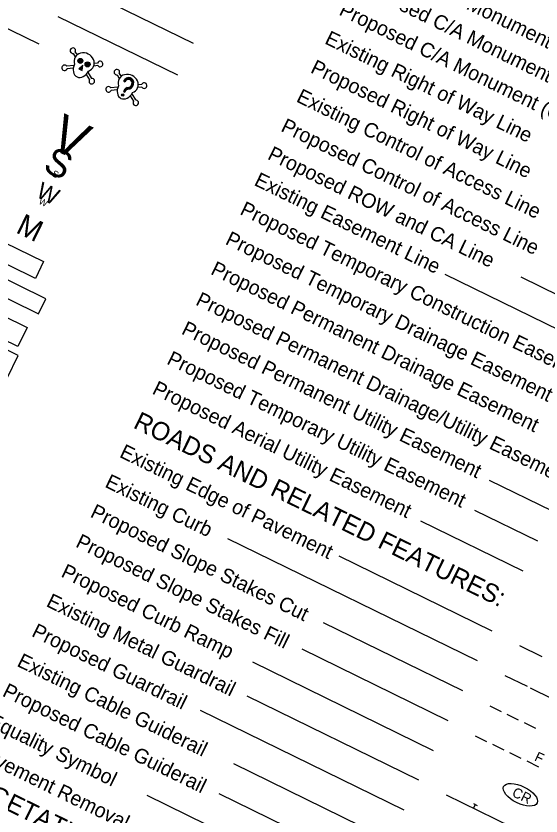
# Model space of a CAD drawing. Extents: x 1517888 to 1526099, y 633375 to 640181.
# Drawn here: x 1522960 to 1523591, y 635991 to 636952 of the extents above; entities that cross this region are included whole.
import ezdxf

# ---------------------------------------------------------------- set-up
doc = ezdxf.new("R2010")
doc.units = 0
doc.layers.add('Default', color=7, linetype='Continuous')

msp = doc.modelspace()

# ---------------------------------------------------------------- linework, layer by layer
at = {"layer": 'Default'}
for p, q in [((1523029.23, 636989.36), (1523172.88, 636919.11)), ((1523010.54, 636951.16), (1523154.2, 636880.91)), ((1522987.81, 636917.75), (1522932.43, 636944.84)), ((1523028.68, 636906.74), (1523031.29, 636902.53)), ((1523031.33, 636908.38), (1523033.44, 636904.98)), ((1523029.74, 636892.25), (1523021.15, 636891.33)), ((1523039.81, 636891.75), (1523039.81, 636891.75)), ((1523058.47, 636892.17), (1523053.54, 636891.65)), ((1523058.14, 636895.28), (1523054.15, 636894.85)), ((1523028.95, 636889.03), (1523021.48, 636888.23)), ((1523044.32, 636881.51), (1523048.28, 636875.12)), ((1523046.38, 636884.11), (1523050.93, 636876.77)), ((1523081.53, 636880.9), (1523084.13, 636876.69)), ((1523084.18, 636882.54), (1523086.29, 636879.13)), ((1523089.24, 636873.55), (1523091.02, 636872.68)), ((1523082.58, 636866.4), (1523073.99, 636865.49)), ((1523081.79, 636863.18), (1523074.32, 636862.39)), ((1523090, 636862.75), (1523089.24, 636861.18)), ((1523089.24, 636861.18), (1523091.02, 636860.31)), ((1523090.25, 636862.63), (1523089.49, 636861.06)), ((1523090.51, 636862.5), (1523089.74, 636860.94)), ((1523090.76, 636862.38), (1523090, 636860.81)), ((1523091.02, 636862.25), (1523090.25, 636860.69)), ((1523091.27, 636862.13), (1523090.51, 636860.56)), ((1523091.53, 636862), (1523090.76, 636860.44)), ((1523091.78, 636861.88), (1523091.02, 636860.31)), ((1523093.1, 636866.82), (1523093.1, 636866.82)), ((1523111.31, 636866.33), (1523106.39, 636865.81)), ((1523110.98, 636869.43), (1523106.99, 636869.01)), ((1523097.16, 636855.67), (1523101.12, 636849.28)), ((1523099.22, 636858.27), (1523103.77, 636850.92)), ((1523691.95, 636535.62), (1523475.96, 636641.25)), ((1523709.43, 636568.49), (1523566.93, 636638.18)), ((1523604.6, 636357.02), (1523528.94, 636394.02)), ((1523587.03, 636321.11), (1523511.37, 636358.11)), ((1523569.47, 636285.19), (1523446.55, 636345.31)), ((1523514.59, 636177.35), (1523214.45, 636324.15)), ((1523532.15, 636213.27), (1523348.37, 636303.15)), ((1523497.03, 636141.44), (1523329.69, 636223.28)), ((1523479.46, 636105.53), (1523303.96, 636191.36)), ((1523564.92, 636195.96), (1523591.86, 636182.79)), ((1523461.9, 636069.62), (1523244.76, 636175.81)), ((1523547.36, 636160.05), (1523574.29, 636146.88)), ((1523577.88, 636145.12), (1523604.82, 636131.95)), ((1523444.16, 636034.06), (1523237.95, 636134.91)), ((1523529.38, 636123.28), (1523543.02, 636116.61)), ((1523426.59, 635998.14), (1523181.96, 636117.79)), ((1523564.03, 636106.33), (1523550.47, 636112.96)), ((1523584.68, 636096.23), (1523571.03, 636102.91)), ((1523511.81, 636087.37), (1523525.46, 636080.7)), ((1523546.47, 636070.42), (1523532.91, 636077.05)), ((1523567.12, 636060.32), (1523553.47, 636067)), ((1523409.03, 635962.23), (1523221.74, 636053.83)), ((1523588.22, 636050), (1523574.21, 636056.85)), ((1523373.9, 635890.41), (1523117.8, 636015.66)), ((1523391.46, 635926.32), (1523204.18, 636017.92)), ((1523476.93, 636016.75), (1523620.58, 635946.49)), ((1523509.89, 636006.19), (1523514.38, 636003.99)), ((1523509.94, 636000.6), (1523512.14, 636005.09))]:
    msp.add_line(p, q, dxfattribs=at)
for points in [[(1523040.25, 636892.67), (1523035.65, 636888.25), (1523039.59, 636886.32)], [(1523039.81, 636891.75), (1523036.26, 636888.35), (1523039.3, 636886.86)], [(1523039.36, 636890.84), (1523036.86, 636888.44), (1523039, 636887.39)], [(1523038.91, 636889.93), (1523037.46, 636888.53), (1523038.7, 636887.93)], [(1523038.47, 636889.01), (1523038.07, 636888.63), (1523038.41, 636888.46)], [(1522930.35, 636687.5), (1522993.2, 636656.76), (1522983.37, 636636.67), (1522920.53, 636667.41)], [(1522888.47, 636642.48), (1522987.23, 636594.18), (1522996.01, 636612.13), (1522897.25, 636660.43)], [(1522882.32, 636622.4), (1522973.65, 636577.73), (1522962.41, 636554.75), (1522871.08, 636599.41)], [(1522850.74, 636565.33), (1522949.5, 636517.03), (1522962.68, 636543.97), (1522937.24, 636556.4), (1522930.66, 636542.94), (1522882.76, 636566.36), (1522889.35, 636579.83), (1522863.92, 636592.27)]]:
    msp.add_lwpolyline(points, close=True, dxfattribs=at)
for centre, radius in [((1523037.42, 636897.84), 2.97), ((1523037.42, 636897.84), 2.62), ((1523037.42, 636897.84), 2.27), ((1523037.42, 636897.84), 1.92), ((1523037.42, 636897.84), 1.57), ((1523037.42, 636897.84), 1.22), ((1523037.42, 636897.84), 0.867), ((1523037.42, 636897.84), 0.518), ((1523037.42, 636897.84), 0.168), ((1523046.08, 636893.61), 2.97), ((1523046.08, 636893.61), 2.62), ((1523046.08, 636893.61), 2.27), ((1523046.08, 636893.61), 1.92), ((1523046.08, 636893.61), 1.57), ((1523046.08, 636893.61), 1.22), ((1523046.08, 636893.61), 0.867), ((1523046.08, 636893.61), 0.518), ((1523046.08, 636893.61), 0.168), ((1523088.3, 636856.85), 1.42), ((1523088.3, 636856.85), 1.1), ((1523088.3, 636856.85), 0.781), ((1523088.3, 636856.85), 0.466), ((1523088.3, 636856.85), 0.151)]:
    msp.add_circle(centre, radius, dxfattribs=at)
for centre, start, end in [((1523028.47, 636910.05), 329.83534, 273.7439), ((1523018.4, 636889.47), 34.13155, 338.04011), ((1523061.21, 636894.04), 214.13155, 158.04011), ((1523081.31, 636884.21), 329.83534, 273.7439), ((1523051.15, 636873.46), 149.83534, 93.7439), ((1523114.05, 636868.19), 214.13155, 158.04011), ((1523071.25, 636863.63), 34.13155, 338.04011), ((1523103.99, 636847.61), 149.83534, 93.7439)]:
    msp.add_arc(centre, 3.32, start, end, dxfattribs=at)
for centre, major_axis, ratio, start_param, end_param in [((1523041.98, 636896.2), (11.17, -5.46), 0.885014, 5.564242, 10.143721), ((1523038.85, 636889.8), (-5.46, -11.17), 0.752542, 4.722735, 7.843636), ((1523094.82, 636870.35), (11.17, -5.46), 0.885014, 5.564242, 10.143721), ((1523095.01, 636870.73), (3.14, 6.41), 0.9, 3.567618, 7.853982), ((1523095.01, 636870.73), (3, 6.13), 0.9, 3.567618, 7.853982), ((1523095.01, 636870.73), (2.86, 5.85), 0.9, 3.567618, 7.853982), ((1523095.01, 636870.73), (2.72, 5.56), 0.9, 3.567618, 7.853982), ((1523095.01, 636870.73), (2.58, 5.28), 0.9, 3.567618, 7.853982), ((1523095.01, 636870.73), (2.44, 5), 0.9, 3.567618, 7.853982), ((1523095.01, 636870.73), (2.31, 4.71), 0.9, 3.567618, 7.853982), ((1523095.01, 636870.73), (2.17, 4.43), 0.9, 3.567618, 7.853982), ((1523091.69, 636863.96), (-5.46, -11.17), 0.752542, 4.722735, 7.843636), ((1523094.33, 636860.63), (2.35, 4.81), 0.9, 0.426026, 1.570796), ((1523094.33, 636860.63), (2.21, 4.53), 0.9, 0.426026, 1.570796), ((1523094.33, 636860.63), (2.07, 4.24), 0.9, 0.426026, 1.570796), ((1523094.33, 636860.63), (1.94, 3.96), 0.9, 0.426026, 1.570796), ((1523094.33, 636860.63), (1.8, 3.68), 0.9, 0.426026, 1.570796), ((1523094.33, 636860.63), (1.66, 3.39), 0.9, 0.426026, 1.570796), ((1523094.33, 636860.63), (1.52, 3.11), 0.9, 0.426026, 1.570796), ((1523094.33, 636860.63), (1.38, 2.83), 0.9, 0.426026, 1.570796)]:
    msp.add_ellipse(centre, major_axis=major_axis, ratio=ratio, start_param=start_param, end_param=end_param, dxfattribs=at)
msp.add_ellipse((1523566.17, 636016.69), major_axis=(20.14, -9.85), ratio=0.462467, dxfattribs=at)

# ---------------------------------------------------------------- texts
for s, height, p in [('Existing Permanent Easement Monument', 17.4903, (1523422.14, 637106.51)), ('Proposed Permanent Easement Monument', 17.4903, (1523406.19, 637073.73)), ('Existing C/A Monument', 17.4903, (1523379.74, 637019.54)), ('Proposed C/A Monument (Rebar and Cap)', 17.4903, (1523363.29, 636986.85)), ('Proposed C/A Monument (Concrete)', 17.4903, (1523347.04, 636953.61)), ('Existing Right of Way Line', 17.4903, (1523329.87, 636919.12)), ('Proposed Right of Way Line', 17.4903, (1523312.85, 636884.33)), ('Existing Control of Access Line', 17.4903, (1523295.76, 636849.38)), ('V', 44.97, (1522998.01, 636794.79)), ('Proposed Control of Access Line', 17.4903, (1523277.23, 636813.98)), ('Proposed ROW and CA Line', 17.4903, (1523261.2, 636780.42)), ('S', 32.98, (1522990.98, 636766.65)), ('S', 8, (1523002.56, 636759.79)), ('Existing Easement Line', 17.4903, (1523245.09, 636749.13)), ('W', 19.99, (1522982.9, 636735.12)), ('W', 8, (1522986.63, 636726.76)), ('Proposed Temporary Construction Easement', 17.4903, (1523228.01, 636714.2)), ('M', 25.49, (1522958.75, 636692.27)), ('Proposed Temporary Drainage Easement', 17.4903, (1523210.44, 636678.29)), ('Proposed Permanent Drainage Easement', 17.4903, (1523192.88, 636642.37)), ('Proposed Permanent Drainage/Utility Easement', 17.4903, (1523174.81, 636605.42)), ('Proposed Permanent Utility Easement', 17.4903, (1523157.74, 636570.53)), ('Proposed Temporary Utility Easement', 17.4903, (1523140.18, 636534.62)), ('Proposed Aerial Utility Easement', 17.4903, (1523122.62, 636498.71)), ('ROADS AND RELATED FEATURES:', 21.9878, (1523099.78, 636457.76)), ('Existing Edge of Pavement', 17.4903, (1523083.29, 636422.67)), ('Existing Curb', 17.4903, (1523065.72, 636386.76)), ('Proposed Slope Stakes Cut', 17.4903, (1523048.16, 636350.85)), ('Proposed Slope Stakes Fill', 17.4903, (1523030.6, 636314.93)), ('Proposed Curb Ramp', 17.4903, (1523013.03, 636279.02)), ('Existing Metal Guardrail', 17.4903, (1522995.29, 636243.46)), ('Proposed Guardrail', 17.4903, (1522977.76, 636207.56)), ('Existing Cable Guiderail', 17.4903, (1522960.2, 636171.65)), ('Proposed Cable Guiderail', 17.4903, (1522942.63, 636135.74)), ('Equality Symbol', 17.4903, (1522925.07, 636099.82)), ('Pavement Removal', 17.4903, (1522907.51, 636063.91)), ('F', 11.85, (1523582.12, 636058.24)), ('VEGETATION:', 21.9878, (1522890.23, 636026.62)), ('CR', 11.993, (1523555.11, 636015.53)), ('Single Tree', 17.4903, (1522872.19, 635990.99))]:
    msp.add_text(s, height=height, rotation=333.93772, dxfattribs=at).set_placement(p)

doc.saveas('drawing.dxf')
